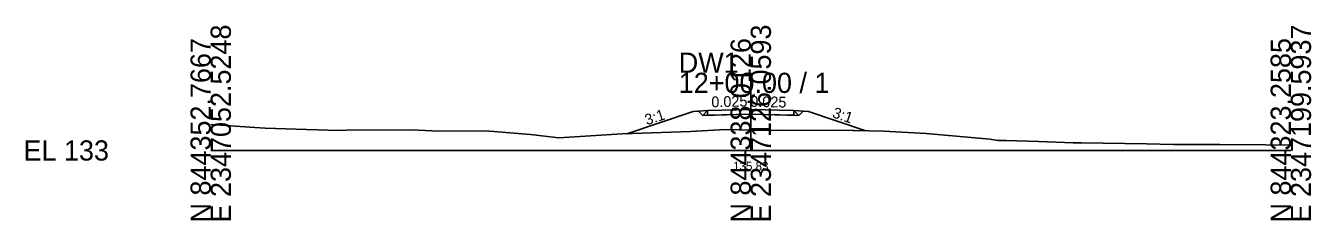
# Model space of a CAD drawing. Extents: x -26 to 2347152, y 490 to 844394.
# Drawn here: x -25.7 to 152.8, y 1990.3 to 2017.3 of the extents above; entities that cross this region are included whole.
import ezdxf

# ---------------------------------------------------------------- set-up
doc = ezdxf.new("R2010")
doc.units = 0
for name, color, linetype in [('Exist Cross Section Cell', 7, 'Continuous'), ('Exist XS Center Line Elevation Label', 7, 'Continuous'), ('Exist XS Ground Line', 7, 'Continuous'), ('Prop CMT Pvmt Course 1', 7, 'Continuous'), ('Prop CMT Pvmt Surface', 7, 'Continuous'), ('Prop CMT Pvmt Surface Shoulder', 7, 'Continuous'), ('Prop CMT Shld Paved Course 1', 7, 'Continuous'), ('Prop CMT Slope Grass', 7, 'Continuous'), ('Prop CMT Subgrade Earthwork', 7, 'Continuous'), ('Prop XS Earthwork Shape', 7, 'Continuous'), ('Prop XS SE Text', 7, 'Continuous'), ('Prop XS Side Slope Text', 7, 'Continuous')]:
    doc.layers.add(name, color=color, linetype=linetype)

msp = doc.modelspace()

# ---------------------------------------------------------------- linework, layer by layer
at = {"layer": 'Exist Cross Section Cell'}
for p, q in [((75, 2000), (75, 2010.79)), ((0, 2000), (75, 2000)), ((75, 2000), (150, 2000))]:
    msp.add_line(p, q, dxfattribs=at)
at = {"layer": 'Exist XS Ground Line'}
msp.add_lwpolyline([(0, 2003.6), (6.11, 2003.19), (7.55, 2003.1), (13.28, 2002.91), (17.75, 2002.79), (18.87, 2002.8), (27.95, 2002.86), (31.63, 2002.68), (38.15, 2002.71), (44.39, 2002.21), (48.35, 2001.74), (57.15, 2002.29), (58.55, 2002.35), (66.64, 2002.65), (71.45, 2002.91), (73.41, 2002.86), (75, 2002.83), (79.1, 2002.76), (87.27, 2002.83), (93.46, 2002.66), (99.35, 2002.34), (108.19, 2001.55), (109.37, 2001.38), (110.45, 2001.4), (114.95, 2001.23), (119.75, 2001.05), (120.95, 2001.04), (129.95, 2000.91), (133.71, 2000.85), (140.15, 2000.82), (146.47, 2000.8), (150, 2000.75)], dxfattribs=at)
at = {"layer": 'Prop CMT Pvmt Course 1'}
for p, q in [((68.32, 2004.87), (75.01, 2005.03)), ((75, 2005.7), (69, 2005.55)), ((69, 2005.55), (69, 2005.3)), ((69, 2004.88), (75.01, 2005.03)), ((79, 2004.93), (74.98, 2005.03)), ((81, 2004.88), (74.98, 2005.03)), ((75, 2005.45), (75, 2005.7)), ((75, 2005.7), (81, 2005.55)), ((75, 2005.45), (75, 2005.7)), ((75, 2005.45), (75, 2005.57)), ((75, 2005.57), (75, 2005.57)), ((75, 2005.57), (75, 2005.45)), ((75, 2005.45), (75, 2005.57)), ((75, 2005.57), (75, 2005.57)), ((75, 2005.57), (75, 2005.45)), ((75, 2005.45), (75, 2005.45)), ((75, 2005.45), (75, 2005.45)), ((81, 2005.55), (81, 2005.3))]:
    msp.add_line(p, q, dxfattribs=at)
for points in [[(75, 2005.7), (69, 2005.55)], [(69, 2005.55), (69, 2004.88)], [(75, 2005.45), (75, 2005.7)], [(75, 2005.7), (81, 2005.55)], [(75, 2005.03), (75, 2005.7)], [(81, 2005.55), (81, 2004.88)]]:
    msp.add_lwpolyline(points, dxfattribs=at)
msp.add_lwpolyline([(75, 2005.45), (75, 2005.57), (75, 2005.57), (75, 2005.45)], close=True, dxfattribs=at)
msp.add_lwpolyline([(75, 2005.45), (75, 2005.57), (75, 2005.57), (75, 2005.45)], close=True, dxfattribs=at)
at = {"layer": 'Prop CMT Pvmt Surface'}
for q in [(69, 2005.55), (81, 2005.55)]:
    msp.add_line((75, 2005.7), q, dxfattribs=at)
for points in [[(75, 2005.7), (69, 2005.55)], [(75, 2005.7), (81, 2005.55)]]:
    msp.add_lwpolyline(points, dxfattribs=at)
at = {"layer": 'Prop CMT Pvmt Surface Shoulder'}
for p, q in [((69, 2005.55), (69, 2005.55)), ((81, 2005.55), (81, 2005.55))]:
    msp.add_line(p, q, dxfattribs=at)
for points in [[(69, 2005.55), (69, 2005.55)], [(81, 2005.55), (81, 2005.55)]]:
    msp.add_lwpolyline(points, dxfattribs=at)
at = {"layer": 'Prop CMT Shld Paved Course 1'}
for p, q in [((69, 2005.55), (68.32, 2004.87)), ((69, 2005.55), (69, 2005.55)), ((69, 2005.3), (69, 2005.55)), ((81, 2005.55), (81, 2005.55)), ((81, 2005.55), (81.68, 2004.87)), ((81, 2005.3), (81, 2005.55)), ((68.74, 2004.87), (69, 2004.88)), ((81.26, 2004.87), (81, 2004.88))]:
    msp.add_line(p, q, dxfattribs=at)
for points in [[(69, 2005.55), (68.32, 2004.87)], [(69, 2005.55), (69, 2005.55)], [(69, 2004.88), (69, 2005.55)], [(81, 2005.55), (81, 2005.55)], [(81, 2005.55), (81.68, 2004.87)], [(81, 2004.88), (81, 2005.55)], [(68.32, 2004.87), (69, 2004.88)], [(81.68, 2004.87), (81, 2004.88)]]:
    msp.add_lwpolyline(points, dxfattribs=at)
at = {"layer": 'Prop CMT Slope Grass'}
for p, q in [((67, 2005.39), (57.8, 2002.32)), ((69, 2005.55), (67, 2005.39)), ((81, 2005.55), (83, 2005.39)), ((83, 2005.39), (90.97, 2002.73))]:
    msp.add_line(p, q, dxfattribs=at)
at = {"layer": 'Prop CMT Subgrade Earthwork'}
for p, q in [((67.74, 2005.44), (68.32, 2004.87)), ((82.26, 2005.44), (81.68, 2004.87))]:
    msp.add_line(p, q, dxfattribs=at)
for points in [[(75.01, 2005.03), (68.32, 2004.87)], [(75.01, 2005.03), (81.68, 2004.87)]]:
    msp.add_lwpolyline(points, dxfattribs=at)
at = {"layer": 'Prop XS Earthwork Shape'}
msp.add_lwpolyline([(82.26, 2005.44), (83, 2005.39), (90.97, 2002.73), (87.27, 2002.83), (79.1, 2002.76), (75, 2002.83), (73.41, 2002.86), (71.45, 2002.91), (66.64, 2002.65), (58.55, 2002.35), (57.8, 2002.32), (67, 2005.39), (67.74, 2005.44), (68.32, 2004.87), (75.01, 2005.03), (81.68, 2004.87)], close=True, dxfattribs=at)

# ---------------------------------------------------------------- texts
at = {"layer": 'Exist Cross Section Cell'}
for s, p in [('E 2347052.5248', (2.8, 1990)), ('E 2347126.0593', (77.8, 1990)), ('E 2347199.5937', (152.8, 1990)), ('N 844352.7667', (0, 1990)), ('N 844338.0126', (75, 1990)), ('N 844323.2585', (150, 1990))]:
    msp.add_text(s, height=2.8, rotation=90, dxfattribs=at).set_placement(p)
for s, p in [('DW1', (65, 2010.79)), ('12+00.00 / 1', (65, 2007.99)), ('EL 133', (-26, 1998.6))]:
    msp.add_text(s, height=2.8, dxfattribs=at).set_placement(p)
at = {"layer": 'Exist XS Center Line Elevation Label'}
msp.add_text('135.83', height=1.2, dxfattribs=at).set_placement((72.55, 1997.23))
at = {"layer": 'Prop XS SE Text'}
for rotation, p in [(1.4321, (69.54, 2005.99)), (358.5679, (74.91, 2006.07))]:
    msp.add_text('0.025', height=1.5, rotation=rotation, dxfattribs=at).set_placement(p)
at = {"layer": 'Prop XS Side Slope Text'}
for rotation, p in [(18.4349, (60.57, 2003.48)), (341.5651, (86.23, 2004.63))]:
    msp.add_text('3:1', height=1.5, rotation=rotation, dxfattribs=at).set_placement(p)

doc.saveas('drawing.dxf')
